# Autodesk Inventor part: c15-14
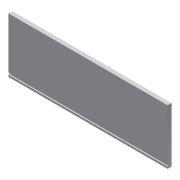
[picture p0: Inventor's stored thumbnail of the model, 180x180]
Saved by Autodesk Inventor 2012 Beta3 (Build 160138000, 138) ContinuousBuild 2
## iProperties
Created: 2011-02
Part Number: c15-14
Material: Default
Document SubType Name: Modeling
Designer: Beta-8540w
Density: 1 g/cm^3
Author: Beta-8540w
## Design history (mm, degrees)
derived "c15-13.ipt"
feature "Solid1::c15-13.ipt" dims "d0" = 10
tag "TaggingFeature1"
body "Solid1"
